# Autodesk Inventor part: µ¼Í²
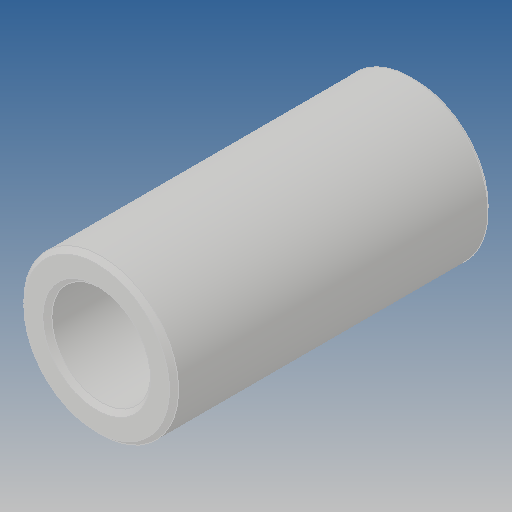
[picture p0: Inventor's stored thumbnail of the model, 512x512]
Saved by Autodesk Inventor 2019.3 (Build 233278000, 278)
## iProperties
Created: 2017-08
Part Number: µ¼Í²
Material: Ogólny
Document SubType Name: Modeling
Designer: Admin
Density: 1 g/cm^3
Appearance: Domyślna
Author: Admin
Revision Number: ÈÎºÎ
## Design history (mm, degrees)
feature "ÊäÈë1"
node "Bryła1"
